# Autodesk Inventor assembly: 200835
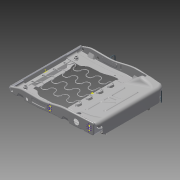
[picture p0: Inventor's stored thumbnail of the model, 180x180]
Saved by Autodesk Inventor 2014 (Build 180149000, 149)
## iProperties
Created: 2007-12
Part Number: 200835
Document SubType Name: Assembly
Designer: MM
Mass: 4124.04 g
Surface Area: 6054.57 cm^2
Volume: 524.766 cm^3
Density: 7.85882 g/cm^3
Description: TOP FRAME ASSEMBLY
Component Category: Lower Component
Author: MM
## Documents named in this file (16)
- C:\Users\iTools\Desktop\tutorial files\Automotive\2000\200835.iam
- C:\Users\iTools\Desktop\tutorial files\Automotive\2000\200136.ipt
- C:\Users\iTools\Desktop\tutorial files\Automotive\2000\201009.ipt
- C:\Users\iTools\Desktop\tutorial files\Automotive\2000\201233.ipt
- C:\Users\iTools\Desktop\tutorial files\Automotive\2000\200654.ipt
- C:\Users\iTools\Desktop\tutorial files\Automotive\2000\200997.ipt
- C:\Users\iTools\Desktop\tutorial files\Automotive\2000\200134.ipt
- C:\Users\iTools\Desktop\tutorial files\Automotive\2000\201054.ipt
- C:\Users\iTools\Desktop\tutorial files\Automotive\2000\200334.ipt
- C:\Users\iTools\Desktop\tutorial files\Automotive\2000\200433.ipt
- C:\Users\iTools\Desktop\tutorial files\Automotive\8000\800683.ipt
- C:\Users\iTools\Desktop\tutorial files\Automotive\8000\801235.ipt
- C:\Users\iTools\Desktop\tutorial files\Automotive\2000\200126.ipt
- C:\Users\iTools\Desktop\tutorial files\Automotive\8000\800587.ipt
- C:\Users\iTools\Desktop\tutorial files\Automotive\8000\800684.ipt
- C:\Users\iTools\Desktop\tutorial files\Automotive\2000\201003_MIR.ipt
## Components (29 placed, 15 different names)
1. 200136:1 — Flush:1, Flush:2, Mate:1, Insert:3, Insert:4, Mate:5, Angle:7
2. 201009:1 — Angle:2, Mate:2, Mate:3, Insert:5, Insert:11, Insert:15
3. 201233:1 — Angle:1, Insert:7, Insert:12, Insert:16
4. 200654:1 — Mate:2, Flush:3, Mate:3, Mate:4
5. 200997:1 — Insert:3, Angle:4, Insert:13, Insert:33
6. 200134:1 — Insert:4, Angle:3, Insert:14, Insert:34
7. 200334:1 — Insert:5, Insert:6
8. 201054:1 — Insert:6, Angle:5, Insert:9, Insert:29
9. 200334:2 — Insert:7, Insert:8
10. 200433:1 — Insert:8, Insert:10, Insert:30
11. 800683:1 — Insert:9
12. 800683:2 — Insert:10
13. 801235:1 — Insert:11
14. 801235:2 — Insert:12
15. 800683:3 — Insert:13
16. 800683:4 — Insert:14
17. 801235:3 — Insert:15
18. 801235:4 — Insert:16
19. 800684:1 — Insert:29, Insert:31
20. 800684:2 — Insert:30, Insert:32
21. 800587:1 — Insert:31
22. 800587:2 — Insert:32
23. 800684:3 — Insert:33
24. 800684:4 — Insert:34
25. 201003_MIR:1
26. 200126:1 — Mate:4, Mate:5, Angle:7
27. 200126:2
28. 200126:3
29. 200126:4
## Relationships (34: Insert 20, Angle 6, Mate 5, Flush 3)
- Flush:1: 200136:1
- Flush:2: 200136:1
- Mate:1: 200136:1
- Angle:1: 201233:1
- Angle:2: 201009:1
- Mate:2: 201009:1 ↔ 200654:1
- Flush:3: 200654:1
- Mate:3: 201009:1 ↔ 200654:1
- Insert:3: 200136:1 ↔ 200997:1
- Insert:4: 200136:1 ↔ 200134:1
- Angle:3: 200134:1
- Angle:4: 200997:1
- Insert:5: 201009:1 ↔ 200334:1
- Insert:6: 200334:1 ↔ 201054:1
- Angle:5: 201054:1
- Insert:7: 201233:1 ↔ 200334:2
- Insert:8: 200334:2 ↔ 200433:1
- Insert:9: 201054:1 ↔ 800683:1
- Insert:10: 200433:1 ↔ 800683:2
- Insert:11: 201009:1 ↔ 801235:1
- Insert:12: 201233:1 ↔ 801235:2
- Insert:13: 200997:1 ↔ 800683:3
- Insert:14: 200134:1 ↔ 800683:4
- Insert:15: 201009:1 ↔ 801235:3
- Insert:16: 201233:1 ↔ 801235:4
- Mate:4: 200654:1 ↔ 200126:1
- Mate:5: 200136:1 ↔ 200126:1
- Angle:7: 200136:1 ↔ 200126:1
- Insert:29: 201054:1 ↔ 800684:1
- Insert:30: 200433:1 ↔ 800684:2
- Insert:31: 800684:1 ↔ 800587:1
- Insert:32: 800684:2 ↔ 800587:2
- Insert:33: 200997:1 ↔ 800684:3
- Insert:34: 200134:1 ↔ 800684:4
